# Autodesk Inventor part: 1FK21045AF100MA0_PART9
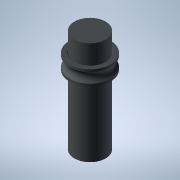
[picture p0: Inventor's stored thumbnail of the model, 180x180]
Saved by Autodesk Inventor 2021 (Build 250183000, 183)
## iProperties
Created: 2025-04
Part Number: 1FK21045AF100MA0_PART9
Material: Generic
Catalog Web Link: www.3dfindit.com
Description: -Servo synchronous motor
Document SubType Name: Modeling
Designer: psAdmin
Mass: 18.6788 g
Surface Area: 52.316 cm^2
Volume: 18.6788 cm^3
Density: 1 g/cm^3
Appearance: PSOLRGB-212-217-219
Category: PARTsolutions
Title: 1FK21045AF100MA0_PART9
Author: Cadenas PARTsolutions
Comments: Servo synchronous motor
Sending System: PARTsolutions
Preprocessor: ST-DEVELOPER v19.3
PSOL_IDENT_0: {$CADENAS_DATA/23d-libs/siemens_ag/_cat_/52/6b/1fk21045af100ma0.prj},213 {VTYP=3D},{NB=1FK21045AF100
PSOL_IDENT_1: MA0_PART9},{LINA=1FK21045AF100MA0_PART9},{NN=1FK21045AF100MA0_PART9},{NOPRJ=TRUE},{DATE=19.08.2025 1
PSOL_IDENT_2: 4:00:38},{GEOMDATE=30.07.2025 02:01:45},{VERSION=},{LINEID=10},{WBVAR=},{WBNUMERIC=}  {NB=1FK21045AF
PSOL_IDENT_3: 100MA0_PART9},{LINA=1FK21045AF100MA0_PART9},{KT=DUMMY},{PREVIEW=../../../_pool_/cb/72/p_d211_xx_0043
PSOL_IDENT_4: 4j.png},{DESCSHORT=SIMOTICS S-1FK2 HD, SINAMICS S210 3AC 400V-480V, 2.4 Nm, 3000 rpm},{DESCLONG=SIMO
PSOL_IDENT_5: TICS S-1FK2 HD servo motor M0=2.4 Nm; PN = 0.75 kW at nN=3000 rpm (380-480 V); PN = 0.375 kW at nN=1
PSOL_IDENT_6: 500 rpm (200-240 V); with holding brake; degree of protection IP64; cylindrical shaft D19x40mm; abso
PSOL_IDENT_7: lute encoder 22-bit + 12-bit multiturn (encoder AM22DQC); with OCC interface; plug size M17, rotatab
PSOL_IDENT_8: le; SIMOTICS S-1FK2 servomotorfor a wide range of uses in industrial environments. SIMOTICS S‑1FK2 s
PSOL_IDENT_9: ervomotors are compact synchronous motors with a high dynamic performance that set themselves apart
PSOL_IDENT_10: as a result of their high power density, degree of protection and overload capability. The motors ar
PSOL_IDENT_11: e available in two variants: as High Dynamic variant (highest dynamic performance as a result of the
PSOL_IDENT_12: low intrinsic moment of inertia for applications demanding a high dynamic performance with low move
PSOL_IDENT_13: d masses) - and as Compact variant (precise and stable closed-loop control for medium up to large mo
PSOL_IDENT_14: ved masses as a result of a medium intrinsic moment of inertia). SIMOTICSS‑1FK2 servomotors fully ex
PSOL_IDENT_15: ploit their strengths in a system with the SINAMICSS210 frequency converter and simple connection us
PSOL_IDENT_16: ing the one cable connection (OCC). Advantages include the short control and positioning times, fast
PSOL_IDENT_17: and precise correction of disturbing quantities as well as stable control with a high dynamic perfo
PSOL_IDENT_18: rmance. The servo motors can be configured to address a wide range of requirements. For example with
PSOL_IDENT_19: and without holding brake, IP64 or IP65 degree of protection, singleturn or multiturn absolute enco
PSOL_IDENT_20: ders - to name just a few. Further, the servomotors are available in different shaft heights extendi
PSOL_IDENT_21: ng from 20 to 100. A shaft sealing ring is available to achieve an IP65 degree of protection and for
PSOL_IDENT_22: subsequent mounting at the motor or as spare part. SIMOTICS - the optimum motor for each and every
PSOL_IDENT_23: motion control application.},{INTNO=804766906411},{SUPPLIERALTNO=1FK2104-5AF10-0MA0},{MANUID=1FK2104
PSOL_IDENT_24: 5AF100MA0},{MANUNAME=Siemens},{MANUTYPEDESC=Synchronous motor 1FK2-HD 2.4 NM},{AAU732=SIMOTICS},{AAO
PSOL_IDENT_25: 057=S-1FK2},{AAU734=SIMOTICS S-1FK2 HD servo motor M0=2.4 Nm; PN = 0.75 kW at nN=3000 rpm (380-480 V
PSOL_IDENT_26: ); PN = 0.375 kW at nN=1500 rpm (200-240 V); with holding brake; degree of protection IP64; cylindri
PSOL_IDENT_27: cal shaft D19x40mm; absolute encoder 22-bit + 12-bit multiturn (encoder AM22DQC); with OCC interface
PSOL_IDENT_28: ; plug size M17, rotatable;},{AAW338=Synchronous motor 1FK2-HD 2.4 NM},{AAO742=SIMOTICS},{AAO663=404
PSOL_IDENT_29: 2948693070},{NOCUPEROU=1},{PRICEQUANTITY=1},{QUANTITYMIN=1},{QUANTITYINT=1},{CTN=85015100},{COO=DE},
PSOL_IDENT_30: {AAO676=1FK2104-5AF10-0MA0},{AAO677=Siemens AG},{ORDERUNIT=C62},{CONTENTUNIT=C62}
NB: 1FK21045AF100MA0_PART9
NT: Servo synchronous motor
NBSYN: $MANUID._PART9
LINA: 1FK21045AF100MA0_PART9
CATALOG: SIEMENS
PREVIEW: ../../../_pool_/cb/72/p_d211_xx_00434j.png
DESCSHORT: SIMOTICS S-1FK2 HD, SINAMICS S210 3AC 400V-480V, 2.4 Nm, 3000 rpm
DESCLONG: SIMOTICS S-1FK2 HD servo motor M0=2.4 Nm; PN = 0.75 kW at nN=3000 rpm (380-480 V); PN = 0.375 kW at nN=1500 rpm (200-240 V); with holding brake; degree of prote
INTNO: 804766906411
SUPPLIERALTNO: 1FK2104-5AF10-0MA0
MANUID: 1FK21045AF100MA0
MANUNAME: Siemens
MANUTYPEDESC: Synchronous motor 1FK2-HD 2.4 NM
AAU732: SIMOTICS
AAO057: S-1FK2
AAU734: SIMOTICS S-1FK2 HD servo motor M0=2.4 Nm; PN = 0.75 kW at nN=3000 rpm (380-480 V); PN = 0.375 kW at nN=1500 rpm (200-240 V); with holding brake; degree of prote
AAW338: Synchronous motor 1FK2-HD 2.4 NM
AAO742: SIMOTICS
AAO663: 4042948693070.0
NOCUPEROU: 1
PRICEQUANTITY: 1
QUANTITYMIN: 1
QUANTITYINT: 1
CTN: 85015100
COO: DE
ARTICLENO: 1FK21045AF100MA0_PART9
BOMINFO: 1FK21045AF100MA0_PART9
CREATOR: CADENAS GmbH
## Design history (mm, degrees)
feature "2025_04_17_15_34_52_0317"
body "Solid1"
